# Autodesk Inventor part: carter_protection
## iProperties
Created: 2011-01
Part Number: carter_protection
Document SubType Name: Modeling
Designer: eric
Density: 1 g/cm^3
Mass: 32.3254 g
Surface Area: 358.699 cm^2
Volume: 32.3254 cm^3
Author: eric
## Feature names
1. Base1
